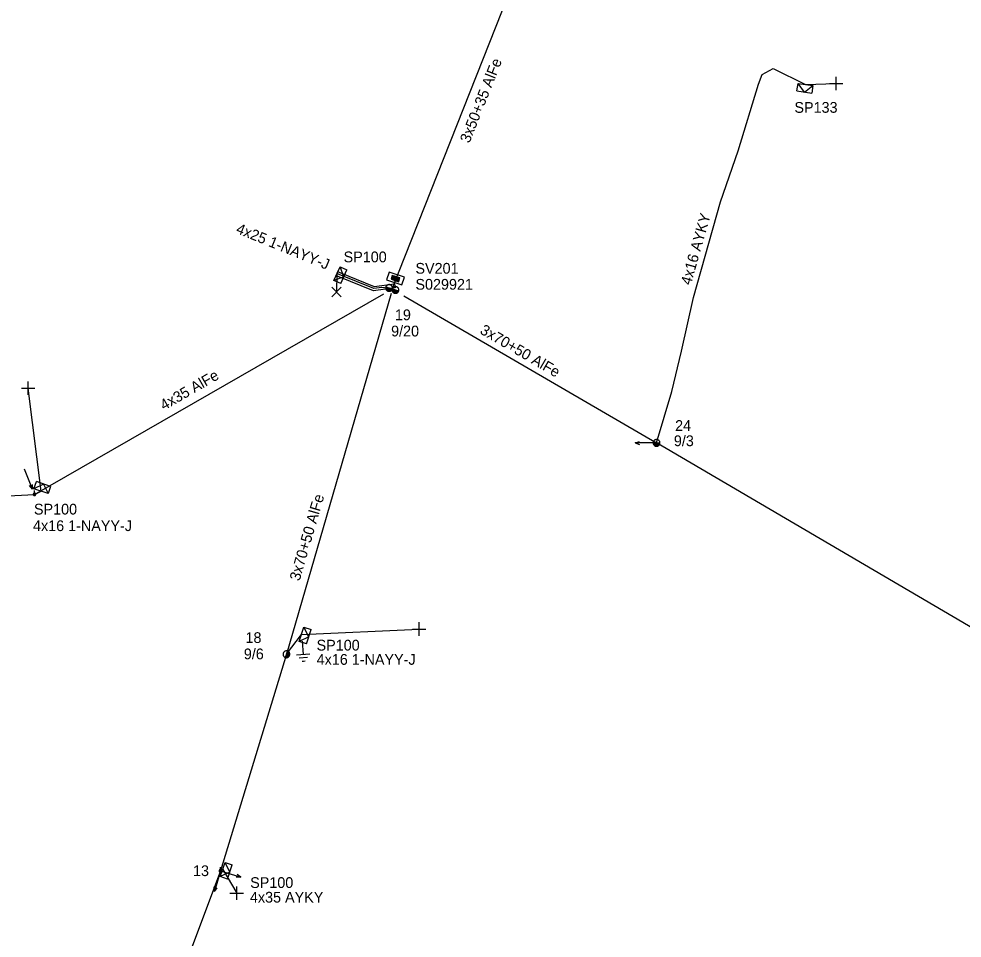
# Model space of a CAD drawing. Extents: x -788458 to -786145, y -1154772 to -1152372.
# Drawn here: x -787405.6 to -787317.8, y -1152992.9 to -1152907.4 of the extents above; entities that cross this region are included whole.
import ezdxf

# ---------------------------------------------------------------- set-up
doc = ezdxf.new("R2010")
doc.units = 0
for name, color, linetype in [('Vrstva 1', 7, 'Continuous'), ('Vrstva 12', 7, 'Continuous'), ('Vrstva 13', 7, 'Continuous'), ('Vrstva 14', 7, 'Continuous'), ('Vrstva 15', 7, 'Continuous'), ('Vrstva 2', 7, 'Continuous'), ('Vrstva 20', 7, 'Continuous'), ('Vrstva 28', 7, 'Continuous'), ('Vrstva 29', 7, 'Continuous'), ('Vrstva 30', 7, 'Continuous'), ('Vrstva 31', 7, 'Continuous'), ('Vrstva 33', 7, 'Continuous'), ('Vrstva 34', 7, 'Continuous'), ('Vrstva 52', 7, 'Continuous'), ('Vrstva 54', 7, 'Continuous'), ('Vrstva 55', 7, 'Continuous'), ('Vrstva 59', 7, 'Continuous'), ('Vrstva 8', 7, 'Continuous'), ('Vrstva 9', 7, 'Continuous')]:
    doc.layers.add(name, color=color, linetype=linetype)

# ---------------------------------------------------------------- blocks, each defined once
blk = doc.blocks.new('NN440')
at = {"layer": 'Vrstva 2'}
for points in [[(0.63, 0), (0.63, 0.06), (0.62, 0.13), (0.6, 0.19), (0.58, 0.25), (0.55, 0.31), (0.51, 0.37), (0.47, 0.42), (0.42, 0.46), (0.37, 0.51), (0.32, 0.54), (0.26, 0.57), (0.2, 0.59), (0.13, 0.61), (0.07, 0.62), (0, 0.63), (-0.06, 0.62), (-0.13, 0.61), (-0.19, 0.59), (-0.26, 0.57), (-0.31, 0.54), (-0.37, 0.51), (-0.42, 0.46), (-0.47, 0.42), (-0.51, 0.37), (-0.54, 0.31), (-0.57, 0.25), (-0.6, 0.19), (-0.62, 0.13), (-0.63, 0.06), (-0.63, 0), (-0.63, -0.07), (-0.62, -0.14), (-0.6, -0.2), (-0.57, -0.26), (-0.54, -0.32), (-0.51, -0.37), (-0.47, -0.43), (-0.42, -0.47), (-0.37, -0.51), (-0.31, -0.55), (-0.26, -0.58), (-0.19, -0.6), (-0.13, -0.62), (-0.06, -0.63), (0, -0.63), (0.07, -0.63), (0.13, -0.62), (0.2, -0.6), (0.26, -0.58), (0.32, -0.55), (0.37, -0.51), (0.42, -0.47), (0.47, -0.43), (0.51, -0.37), (0.55, -0.32), (0.58, -0.26), (0.6, -0.2), (0.62, -0.14), (0.63, -0.07), (0.63, 0)], [(-0.63, 0), (0.63, 0)], [(-0.6, -0.18), (0.57, -0.18)], [(-0.51, -0.32), (0.5, -0.32)], [(-0.37, -0.47), (0.35, -0.47)]]:
    blk.add_lwpolyline(points, dxfattribs=at)
blk = doc.blocks.new('NN450')
at = {"layer": 'Vrstva 2'}
for points in [[(0, 0), (0, 0.07), (-0.01, 0.13), (-0.03, 0.19), (-0.05, 0.25), (-0.08, 0.31), (-0.12, 0.37), (-0.16, 0.42), (-0.21, 0.46), (-0.26, 0.51), (-0.31, 0.54), (-0.37, 0.57), (-0.43, 0.59), (-0.5, 0.61), (-0.56, 0.62), (-0.63, 0.62), (-0.69, 0.62), (-0.75, 0.61), (-0.82, 0.59), (-0.88, 0.57), (-0.94, 0.54), (-0.99, 0.51), (-1.04, 0.46), (-1.09, 0.42), (-1.13, 0.37), (-1.17, 0.31), (-1.2, 0.25), (-1.22, 0.19), (-1.24, 0.13), (-1.25, 0.07), (-1.25, 0), (-1.25, -0.07), (-1.24, -0.13), (-1.22, -0.19), (-1.2, -0.25), (-1.17, -0.31), (-1.13, -0.37), (-1.09, -0.42), (-1.04, -0.46), (-0.99, -0.51), (-0.94, -0.54), (-0.88, -0.57), (-0.82, -0.59), (-0.75, -0.61), (-0.69, -0.62), (-0.62, -0.63), (-0.56, -0.62), (-0.5, -0.61), (-0.43, -0.59), (-0.37, -0.57), (-0.31, -0.54), (-0.26, -0.51), (-0.21, -0.46), (-0.16, -0.42), (-0.12, -0.37), (-0.08, -0.31), (-0.05, -0.25), (-0.03, -0.19), (-0.01, -0.13), (0, -0.07), (0, 0)], [(1.25, 0), (1.25, 0.07), (1.24, 0.13), (1.22, 0.19), (1.2, 0.25), (1.17, 0.31), (1.13, 0.37), (1.09, 0.42), (1.04, 0.46), (0.99, 0.51), (0.94, 0.54), (0.88, 0.57), (0.82, 0.59), (0.75, 0.61), (0.69, 0.62), (0.62, 0.62), (0.56, 0.62), (0.5, 0.61), (0.43, 0.59), (0.37, 0.57), (0.31, 0.54), (0.26, 0.51), (0.21, 0.46), (0.16, 0.42), (0.12, 0.37), (0.08, 0.31), (0.05, 0.25), (0.03, 0.19), (0.01, 0.13), (0, 0.07), (0, 0), (0, -0.07), (0.01, -0.13), (0.03, -0.19), (0.05, -0.25), (0.08, -0.31), (0.12, -0.37), (0.16, -0.42), (0.21, -0.46), (0.26, -0.51), (0.31, -0.54), (0.37, -0.57), (0.43, -0.59), (0.5, -0.61), (0.56, -0.62), (0.63, -0.63), (0.69, -0.62), (0.75, -0.61), (0.82, -0.59), (0.88, -0.57), (0.94, -0.54), (0.99, -0.51), (1.04, -0.46), (1.09, -0.42), (1.13, -0.37), (1.17, -0.31), (1.2, -0.25), (1.22, -0.19), (1.24, -0.13), (1.25, -0.07), (1.25, 0)], [(-1.25, 0), (1.25, 0)], [(-1.23, -0.16), (-0.02, -0.16)], [(-1.16, -0.32), (-0.09, -0.32)], [(-1.03, -0.47), (-0.22, -0.47)], [(0.02, -0.16), (1.23, -0.16)], [(0.09, -0.32), (1.16, -0.32)], [(0.22, -0.47), (1.03, -0.47)]]:
    blk.add_lwpolyline(points, dxfattribs=at)
blk = doc.blocks.new('NN560')
at = {"layer": 'Vrstva 2'}
for points in [[(1.999, -0.001), (1.59, 0.141)], [(0, -0.001), (1.999, -0.001)], [(1.999, -0.001), (1.59, -0.134)]]:
    blk.add_lwpolyline(points, dxfattribs=at)
blk = doc.blocks.new('NN565')
at = {"layer": 'Vrstva 2'}
for points in [[(0.015, 0.528), (0.015, 2.528)], [(0.157, 0.937), (0.015, 0.528), (-0.119, 0.937)]]:
    blk.add_lwpolyline(points, dxfattribs=at)
blk = doc.blocks.new('NN800')
at = {"layer": 'Vrstva 1'}
for points in [[(-0.442, 0.442), (0.442, -0.442)], [(-0.442, -0.442), (0.442, 0.442)]]:
    blk.add_lwpolyline(points, dxfattribs=at)
blk = doc.blocks.new('NN620')
at = {"layer": 'Vrstva 8'}
for points in [[(0.752, 0.004), (-0.748, 0.004)], [(-0.748, 0.004), (-0.748, -0.746)], [(0.752, -0.746), (0.752, 0.004)], [(-0.748, -0.746), (0.752, -0.746)], [(0.368, -0.18), (-0.376, -0.18)], [(-0.376, -0.18), (-0.376, -0.558)], [(-0.376, -0.558), (0.368, -0.558)], [(0.321, -0.227), (-0.329, -0.227)], [(-0.329, -0.227), (-0.329, -0.51)], [(-0.329, -0.51), (0.321, -0.51)], [(0.274, -0.274), (-0.281, -0.274)], [(-0.281, -0.274), (-0.281, -0.463)], [(-0.281, -0.463), (0.274, -0.463)], [(0.227, -0.321), (-0.234, -0.321)], [(-0.234, -0.321), (-0.234, -0.416)], [(-0.234, -0.416), (0.227, -0.416)], [(-0.193, -0.369), (0.185, -0.369)], [(0.227, -0.416), (0.227, -0.321)], [(0.274, -0.463), (0.274, -0.274)], [(0.321, -0.51), (0.321, -0.227)], [(0.368, -0.558), (0.368, -0.18)]]:
    blk.add_lwpolyline(points, dxfattribs=at)
blk = doc.blocks.new('NN630')
at = {"layer": 'Vrstva 9'}
for points in [[(-0.003, -0.7), (-0.703, 0)], [(-0.703, -0.7), (-0.703, 0), (0.697, 0), (0.697, -0.7)], [(-0.703, -0.7), (0.697, -0.7)], [(-0.003, -0.7), (0.697, 0)]]:
    blk.add_lwpolyline(points, dxfattribs=at)
blk = doc.blocks.new('NN810')
at = {"layer": 'Vrstva 14'}
for points in [[(0.004, -0.64), (0.004, -1.89)], [(0.629, -1.89), (-0.621, -1.89)], [(0.388, -2.2), (-0.399, -2.2)], [(0.004, -2.515), (-0.124, -2.515)], [(0.137, -2.515), (0.004, -2.515)]]:
    blk.add_lwpolyline(points, dxfattribs=at)
blk = doc.blocks.new('NN500')
at = {"layer": 'Vrstva 2'}
for points in [[(0, -0.24), (0.02, -0.23), (0.05, -0.23), (0.07, -0.22), (0.09, -0.22), (0.12, -0.2), (0.14, -0.19), (0.16, -0.18), (0.17, -0.16), (0.19, -0.14), (0.2, -0.12), (0.21, -0.1), (0.22, -0.07), (0.23, -0.05), (0.23, -0.02), (0.23, 0), (0.23, 0.02), (0.23, 0.05), (0.22, 0.07), (0.21, 0.1), (0.2, 0.12), (0.19, 0.14), (0.17, 0.16), (0.16, 0.17), (0.14, 0.19), (0.12, 0.2), (0.09, 0.21), (0.07, 0.22), (0.05, 0.23), (0.02, 0.23), (0, 0.23), (-0.03, 0.23), (-0.05, 0.23), (-0.07, 0.22), (-0.1, 0.21), (-0.12, 0.2), (-0.14, 0.19), (-0.16, 0.17), (-0.18, 0.16), (-0.19, 0.14), (-0.2, 0.12), (-0.22, 0.1), (-0.22, 0.07), (-0.23, 0.05), (-0.23, 0.02), (-0.24, 0), (-0.23, -0.02), (-0.23, -0.05), (-0.22, -0.07), (-0.22, -0.1), (-0.2, -0.12), (-0.19, -0.14), (-0.18, -0.16), (-0.16, -0.18), (-0.14, -0.19), (-0.12, -0.2), (-0.1, -0.22), (-0.07, -0.22), (-0.05, -0.23), (-0.03, -0.23), (0, -0.24)], [(0, -0.24), (0.02, -0.23), (0.05, -0.23), (0.07, -0.22), (0.09, -0.22), (0.12, -0.2), (0.14, -0.19), (0.16, -0.18), (0.17, -0.16), (0.19, -0.14), (0.2, -0.12), (0.21, -0.1), (0.22, -0.07), (0.23, -0.05), (0.23, -0.02), (0.23, 0), (0.23, 0.02), (0.23, 0.05), (0.22, 0.07), (0.21, 0.1), (0.2, 0.12), (0.19, 0.14), (0.17, 0.16), (0.16, 0.17), (0.14, 0.19), (0.12, 0.2), (0.09, 0.21), (0.07, 0.22), (0.05, 0.23), (0.02, 0.23), (0, 0.23), (-0.03, 0.23), (-0.05, 0.23), (-0.07, 0.22), (-0.1, 0.21), (-0.12, 0.2), (-0.14, 0.19), (-0.16, 0.17), (-0.18, 0.16), (-0.19, 0.14), (-0.2, 0.12), (-0.22, 0.1), (-0.22, 0.07), (-0.23, 0.05), (-0.23, 0.02), (-0.24, 0), (-0.23, -0.02), (-0.23, -0.05), (-0.22, -0.07), (-0.22, -0.1), (-0.2, -0.12), (-0.19, -0.14), (-0.18, -0.16), (-0.16, -0.18), (-0.14, -0.19), (-0.12, -0.2), (-0.1, -0.22), (-0.07, -0.22), (-0.05, -0.23), (-0.03, -0.23), (0, -0.24)], [(0, -0.21), (0.02, -0.2), (0.04, -0.2), (0.06, -0.2), (0.08, -0.19), (0.1, -0.18), (0.12, -0.17), (0.14, -0.15), (0.15, -0.14), (0.16, -0.12), (0.18, -0.1), (0.19, -0.08), (0.19, -0.06), (0.2, -0.04), (0.2, -0.02), (0.2, 0), (0.2, 0.02), (0.2, 0.04), (0.19, 0.06), (0.19, 0.08), (0.18, 0.1), (0.16, 0.12), (0.15, 0.14), (0.14, 0.15), (0.12, 0.17), (0.1, 0.18), (0.08, 0.19), (0.06, 0.19), (0.04, 0.2), (0.02, 0.2), (0, 0.2), (-0.02, 0.2), (-0.04, 0.2), (-0.06, 0.19), (-0.08, 0.19), (-0.1, 0.18), (-0.12, 0.17), (-0.14, 0.15), (-0.15, 0.14), (-0.17, 0.12), (-0.18, 0.1), (-0.19, 0.08), (-0.2, 0.06), (-0.2, 0.04), (-0.21, 0.02), (-0.21, 0), (-0.21, -0.02), (-0.2, -0.04), (-0.2, -0.06), (-0.19, -0.08), (-0.18, -0.1), (-0.17, -0.12), (-0.15, -0.14), (-0.14, -0.15), (-0.12, -0.17), (-0.1, -0.18), (-0.08, -0.19), (-0.06, -0.2), (-0.04, -0.2), (-0.02, -0.2), (0, -0.21)], [(0, -0.18), (0.02, -0.18), (0.04, -0.17), (0.05, -0.17), (0.07, -0.16), (0.09, -0.15), (0.1, -0.14), (0.12, -0.13), (0.13, -0.12), (0.14, -0.1), (0.15, -0.09), (0.16, -0.07), (0.17, -0.05), (0.17, -0.04), (0.17, -0.02), (0.17, 0), (0.17, 0.02), (0.17, 0.04), (0.17, 0.05), (0.16, 0.07), (0.15, 0.09), (0.14, 0.1), (0.13, 0.12), (0.12, 0.13), (0.1, 0.14), (0.09, 0.15), (0.07, 0.16), (0.05, 0.17), (0.04, 0.17), (0.02, 0.17), (0, 0.18), (-0.02, 0.17), (-0.04, 0.17), (-0.06, 0.17), (-0.07, 0.16), (-0.09, 0.15), (-0.1, 0.14), (-0.12, 0.13), (-0.13, 0.12), (-0.14, 0.1), (-0.15, 0.09), (-0.16, 0.07), (-0.17, 0.05), (-0.17, 0.04), (-0.18, 0.02), (-0.18, 0), (-0.18, -0.02), (-0.17, -0.04), (-0.17, -0.05), (-0.16, -0.07), (-0.15, -0.09), (-0.14, -0.1), (-0.13, -0.12), (-0.12, -0.13), (-0.1, -0.14), (-0.09, -0.15), (-0.07, -0.16), (-0.06, -0.17), (-0.04, -0.17), (-0.02, -0.18), (0, -0.18)], [(0, -0.15), (0.01, -0.15), (0.03, -0.14), (0.04, -0.14), (0.06, -0.13), (0.07, -0.13), (0.08, -0.12), (0.1, -0.11), (0.11, -0.1), (0.12, -0.09), (0.13, -0.07), (0.13, -0.06), (0.14, -0.05), (0.14, -0.03), (0.14, -0.02), (0.14, 0), (0.14, 0.01), (0.14, 0.03), (0.14, 0.04), (0.13, 0.06), (0.13, 0.07), (0.12, 0.09), (0.11, 0.1), (0.1, 0.11), (0.08, 0.12), (0.07, 0.13), (0.06, 0.13), (0.04, 0.14), (0.03, 0.14), (0.01, 0.14), (0, 0.15), (-0.02, 0.14), (-0.03, 0.14), (-0.05, 0.14), (-0.06, 0.13), (-0.07, 0.13), (-0.09, 0.12), (-0.1, 0.11), (-0.11, 0.1), (-0.12, 0.09), (-0.13, 0.07), (-0.13, 0.06), (-0.14, 0.04), (-0.14, 0.03), (-0.15, 0.01), (-0.15, 0), (-0.15, -0.02), (-0.14, -0.03), (-0.14, -0.05), (-0.13, -0.06), (-0.13, -0.07), (-0.12, -0.09), (-0.11, -0.1), (-0.1, -0.11), (-0.09, -0.12), (-0.07, -0.13), (-0.06, -0.13), (-0.05, -0.14), (-0.03, -0.14), (-0.02, -0.15), (0, -0.15)], [(0, -0.12), (0.01, -0.12), (0.02, -0.11), (0.03, -0.11), (0.05, -0.11), (0.06, -0.1), (0.07, -0.09), (0.08, -0.09), (0.09, -0.08), (0.09, -0.07), (0.1, -0.06), (0.11, -0.05), (0.11, -0.04), (0.11, -0.02), (0.11, -0.01), (0.12, 0), (0.11, 0.01), (0.11, 0.02), (0.11, 0.04), (0.11, 0.05), (0.1, 0.06), (0.09, 0.07), (0.09, 0.08), (0.08, 0.09), (0.07, 0.09), (0.06, 0.1), (0.05, 0.11), (0.03, 0.11), (0.02, 0.11), (0.01, 0.12), (0, 0.12), (-0.01, 0.12), (-0.03, 0.11), (-0.04, 0.11), (-0.05, 0.11), (-0.06, 0.1), (-0.07, 0.09), (-0.08, 0.09), (-0.09, 0.08), (-0.1, 0.07), (-0.1, 0.06), (-0.11, 0.05), (-0.11, 0.04), (-0.12, 0.02), (-0.12, 0.01), (-0.12, 0), (-0.12, -0.01), (-0.12, -0.02), (-0.11, -0.04), (-0.11, -0.05), (-0.1, -0.06), (-0.1, -0.07), (-0.09, -0.08), (-0.08, -0.09), (-0.07, -0.09), (-0.06, -0.1), (-0.05, -0.11), (-0.04, -0.11), (-0.03, -0.11), (-0.01, -0.12), (0, -0.12)], [(0, -0.09), (0.01, -0.09), (0.02, -0.09), (0.03, -0.08), (0.03, -0.08), (0.04, -0.08), (0.05, -0.07), (0.06, -0.07), (0.06, -0.06), (0.07, -0.05), (0.07, -0.04), (0.08, -0.04), (0.08, -0.03), (0.08, -0.02), (0.09, -0.01), (0.09, 0), (0.09, 0.01), (0.08, 0.02), (0.08, 0.03), (0.08, 0.03), (0.07, 0.04), (0.07, 0.05), (0.06, 0.06), (0.06, 0.06), (0.05, 0.07), (0.04, 0.07), (0.03, 0.08), (0.03, 0.08), (0.02, 0.08), (0.01, 0.09), (0, 0.09), (-0.01, 0.09), (-0.02, 0.08), (-0.03, 0.08), (-0.04, 0.08), (-0.04, 0.07), (-0.05, 0.07), (-0.06, 0.06), (-0.07, 0.06), (-0.07, 0.05), (-0.08, 0.04), (-0.08, 0.03), (-0.08, 0.03), (-0.09, 0.02), (-0.09, 0.01), (-0.09, 0), (-0.09, -0.01), (-0.09, -0.02), (-0.08, -0.03), (-0.08, -0.04), (-0.08, -0.04), (-0.07, -0.05), (-0.07, -0.06), (-0.06, -0.07), (-0.05, -0.07), (-0.04, -0.08), (-0.04, -0.08), (-0.03, -0.08), (-0.02, -0.09), (-0.01, -0.09), (0, -0.09)], [(0, -0.06), (0, -0.06), (0.01, -0.06), (0.02, -0.05), (0.02, -0.05), (0.03, -0.05), (0.03, -0.05), (0.04, -0.04), (0.04, -0.04), (0.05, -0.03), (0.05, -0.03), (0.05, -0.02), (0.05, -0.02), (0.05, -0.01), (0.06, -0.01), (0.06, 0), (0.06, 0.01), (0.05, 0.01), (0.05, 0.02), (0.05, 0.02), (0.05, 0.03), (0.05, 0.03), (0.04, 0.04), (0.04, 0.04), (0.03, 0.05), (0.03, 0.05), (0.02, 0.05), (0.02, 0.05), (0.01, 0.06), (0, 0.06), (0, 0.06), (-0.01, 0.06), (-0.01, 0.06), (-0.02, 0.05), (-0.02, 0.05), (-0.03, 0.05), (-0.03, 0.05), (-0.04, 0.04), (-0.04, 0.04), (-0.05, 0.03), (-0.05, 0.03), (-0.05, 0.02), (-0.06, 0.02), (-0.06, 0.01), (-0.06, 0.01), (-0.06, 0), (-0.06, -0.01), (-0.06, -0.01), (-0.06, -0.02), (-0.05, -0.02), (-0.05, -0.03), (-0.05, -0.03), (-0.04, -0.04), (-0.04, -0.04), (-0.03, -0.05), (-0.03, -0.05), (-0.02, -0.05), (-0.02, -0.05), (-0.01, -0.06), (-0.01, -0.06), (0, -0.06)], [(0, -0.03), (0, -0.03), (0, -0.03), (0.01, -0.03), (0.01, -0.03), (0.01, -0.02), (0.02, -0.02), (0.02, -0.02), (0.02, -0.02), (0.02, -0.02), (0.02, -0.01), (0.02, -0.01), (0.03, -0.01), (0.03, -0.01), (0.03, 0), (0.03, 0), (0.03, 0), (0.03, 0.01), (0.03, 0.01), (0.02, 0.01), (0.02, 0.01), (0.02, 0.02), (0.02, 0.02), (0.02, 0.02), (0.02, 0.02), (0.01, 0.02), (0.01, 0.02), (0.01, 0.03), (0, 0.03), (0, 0.03), (0, 0.03), (0, 0.03), (-0.01, 0.03), (-0.01, 0.03), (-0.01, 0.02), (-0.02, 0.02), (-0.02, 0.02), (-0.02, 0.02), (-0.02, 0.02), (-0.02, 0.02), (-0.03, 0.01), (-0.03, 0.01), (-0.03, 0.01), (-0.03, 0.01), (-0.03, 0), (-0.03, 0), (-0.03, 0), (-0.03, -0.01), (-0.03, -0.01), (-0.03, -0.01), (-0.03, -0.01), (-0.02, -0.02), (-0.02, -0.02), (-0.02, -0.02), (-0.02, -0.02), (-0.02, -0.02), (-0.01, -0.03), (-0.01, -0.03), (-0.01, -0.03), (0, -0.03), (0, -0.03)], [(0.23, 0), (0.7, 0)]]:
    blk.add_lwpolyline(points, dxfattribs=at)

msp = doc.modelspace()

# ---------------------------------------------------------------- linework, layer by layer
at = {"layer": 'Vrstva 1'}
for points in [[(-787370.84, -1152932.51), (-787352.71, -1152886.68), (-787338.36, -1152850.84), (-787331.68, -1152810.84), (-787329.05, -1152772.02), (-787318.461, -1152738.272)], [(-787427.977, -1152952.863), (-787404.16, -1152951.63), (-787371.618, -1152932.956)], [(-787370.958, -1152932.918), (-787380.7, -1152966.52), (-787386.85, -1152986.69), (-787396.63, -1153012.79)], [(-787369.755, -1152933.142), (-787346.23, -1152946.84)], [(-787192.48, -1153009.24), (-787217.55, -1153001.28), (-787251.42, -1152991.85), (-787285.63, -1152982.28), (-787313.04, -1152966.29), (-787346.23, -1152946.84)]]:
    msp.add_lwpolyline(points, dxfattribs=at)
at = {"layer": 'Vrstva 20'}
msp.add_lwpolyline([(-787375.916, -1152930.894), (-787375.715, -1152930.974), (-787372.533, -1152932.265), (-787370.635, -1152932.022), (-787370.585, -1152932.418), (-787372.587, -1152932.675), (-787375.865, -1152931.346), (-787376.064, -1152931.266)], close=True, dxfattribs=at)
at = {"layer": 'Vrstva 52'}
for points in [[(-787346.23, -1152946.84), (-787344.81, -1152942.06), (-787343.91, -1152938.29), (-787342.8, -1152933.3), (-787340.28, -1152924.4), (-787338.64, -1152919.65), (-787336.74, -1152913.45), (-787336.38, -1152912.53), (-787335.37, -1152911.98), (-787332.36, -1152913.48)], [(-787370.84, -1152932.51), (-787371.815, -1152932.375), (-787372.56, -1152932.47), (-787375.79, -1152931.16), (-787375.99, -1152931.08)], [(-787380.7, -1152966.52), (-787379.29, -1152964.67)], [(-787386.85, -1152986.69), (-787386.63, -1152986.56)]]:
    msp.add_lwpolyline(points, dxfattribs=at)
at = {"layer": 'Vrstva 59'}
for points in [[(-787332.36, -1152913.48), (-787329.5, -1152913.38)], [(-787375.99, -1152931.08), (-787376.036, -1152932.79)], [(-787403.55, -1152951.33), (-787404.75, -1152941.75)], [(-787379.29, -1152964.67), (-787368.326, -1152964.17)], [(-787386.63, -1152986.56), (-787385.33, -1152988.77)]]:
    msp.add_lwpolyline(points, dxfattribs=at)
at = {"layer": 'Vrstva 8'}
msp.add_lwpolyline([(-787404.16, -1152951.63), (-787403.55, -1152951.33)], dxfattribs=at)

# ---------------------------------------------------------------- block references
at = {"layer": 'Vrstva 13', "xscale": 0.5}
for name, p, yscale, rotation in [('NN450', (-787370.84, -1152932.51), 0.5000000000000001, -17.368488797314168), ('NN500', (-787404.16, -1152951.63), 0.5, 90), ('NN440', (-787380.7, -1152966.52), 0.5, 72.74607499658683), ('NN500', (-787386.85, -1152986.69), 0.5, 90)]:
    msp.add_blockref(name, p, dxfattribs=dict(at, yscale=yscale, rotation=rotation))
at = {"layer": 'Vrstva 13', "xscale": 0.5, "yscale": 0.5}
msp.add_blockref('NN440', (-787346.23, -1152946.84), dxfattribs=at)
at = {"layer": 'Vrstva 13'}
for name, p, rotation in [('NN560', (-787346.23, -1152946.84), 180), ('NN565', (-787404.16, -1152951.63), 21.96264164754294), ('NN560', (-787386.85, -1152986.69), -105.82392224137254), ('NN560', (-787386.85, -1152986.69), -17.009691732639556)]:
    msp.add_blockref(name, p, dxfattribs=dict(at, rotation=rotation))
at = {"layer": 'Vrstva 15', "rotation": 4.373844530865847}
msp.add_blockref('NN810', (-787379.29, -1152964.67), dxfattribs=at)
at = {"layer": 'Vrstva 28', "rotation": 162.06326242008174}
msp.add_blockref('NN620', (-787370.658, -1152931.886), dxfattribs=at)
at = {"layer": 'Vrstva 31'}
for p, rotation in [((-787332.36, -1152913.48), -8.334364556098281), ((-787375.99, -1152931.08), 65.90798044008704), ((-787403.55, -1152951.33), 160.87105819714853), ((-787379.29, -1152964.67), 71.91655468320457), ((-787386.63, -1152986.56), 70.7802265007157)]:
    msp.add_blockref('NN630', p, dxfattribs=dict(at, rotation=rotation))
at = {"layer": 'Vrstva 34'}
for p, rotation in [((-787329.5, -1152913.38), 45), ((-787404.75, -1152941.75), 45), ((-787368.326, -1152964.17), 45), ((-787385.33, -1152988.77), 44.99999995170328)]:
    msp.add_blockref('NN800', p, dxfattribs=dict(at, rotation=rotation))
msp.add_blockref('NN800', (-787376.036, -1152932.79), dxfattribs=at)

# ---------------------------------------------------------------- texts
at = {"layer": 'Vrstva 12'}
for s, p in [('9/20', (-787370.951, -1152936.926)), ('9/3', (-787344.618, -1152947.144)), ('9/6', (-787384.663, -1152966.985))]:
    msp.add_text(s, height=1, dxfattribs=at).set_placement(p)
at = {"layer": 'Vrstva 14'}
for s, p in [('19', (-787370.594, -1152935.418)), ('24', (-787344.502, -1152945.723)), ('18', (-787384.509, -1152965.468)), ('13', (-787389.397, -1152987.174))]:
    msp.add_text(s, height=1, dxfattribs=at).set_placement(p)
at = {"layer": 'Vrstva 2'}
for s, rotation, p in [('3x50+35 AlFe', 68.417, (-787363.653, -1152918.983)), ('3x70+50 AlFe', 329.788, (-787362.753, -1152936.606)), ('4x35 AlFe', 29.921, (-787392.107, -1152943.841)), ('3x70+50 AlFe', 73.832, (-787379.471, -1152959.746))]:
    msp.add_text(s, height=1, rotation=rotation, dxfattribs=at).set_placement(p)
at = {"layer": 'Vrstva 29'}
msp.add_text('S029921', height=1, dxfattribs=at).set_placement((-787368.684, -1152932.576))
at = {"layer": 'Vrstva 30'}
msp.add_text('SV201', height=1, dxfattribs=at).set_placement((-787368.684, -1152931.085))
at = {"layer": 'Vrstva 33'}
for s, p in [('SP133', (-787333.391, -1152916.107)), ('SP100', (-787375.373, -1152930.023)), ('SP100', (-787404.209, -1152953.509)), ('SP100', (-787377.89, -1152966.171)), ('SP100', (-787384.075, -1152988.274))]:
    msp.add_text(s, height=1, dxfattribs=at).set_placement(p)
at = {"layer": 'Vrstva 54'}
for s, rotation, p in [('4x16 AYKY', 74.191, (-787343.043, -1152932.211)), ('4x25 1-NAYY-J', 337.924, (-787385.471, -1152927.274))]:
    msp.add_text(s, height=1, rotation=rotation, dxfattribs=at).set_placement(p)
for s, p in [('4x16 1-NAYY-J', (-787377.883, -1152967.499)), ('4x35 AYKY', (-787384.097, -1152989.637))]:
    msp.add_text(s, height=1, dxfattribs=at).set_placement(p)
at = {"layer": 'Vrstva 55'}
msp.add_text('4x16 1-NAYY-J', height=1, dxfattribs=at).set_placement((-787404.297, -1152955.049))

doc.saveas('drawing.dxf')
